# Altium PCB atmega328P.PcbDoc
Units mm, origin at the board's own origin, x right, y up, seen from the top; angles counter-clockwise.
Board outline 71.5 x 56.39 mm, 2 copper layers (Top Layer, Bottom Layer); 14 components, 27 nets, 83 pads, 0 vias.
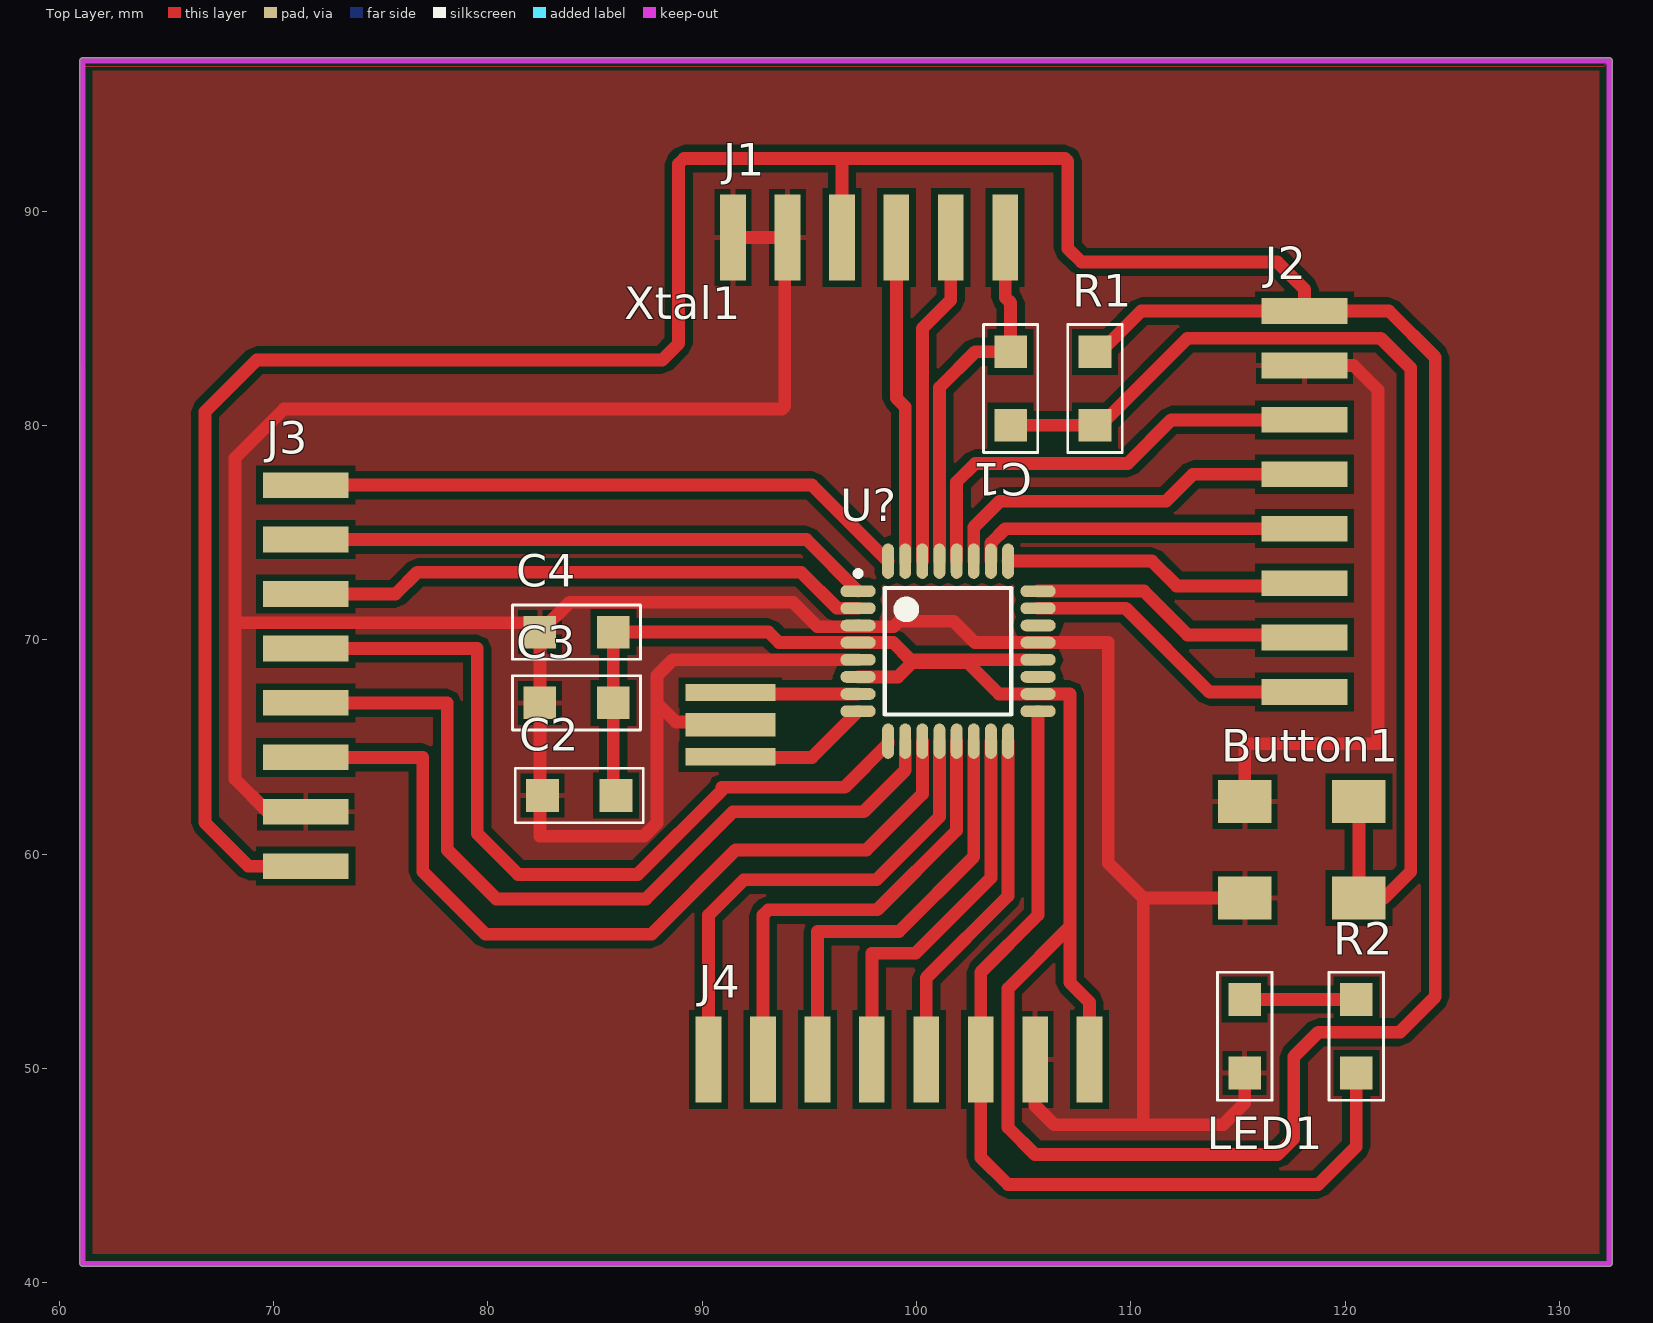
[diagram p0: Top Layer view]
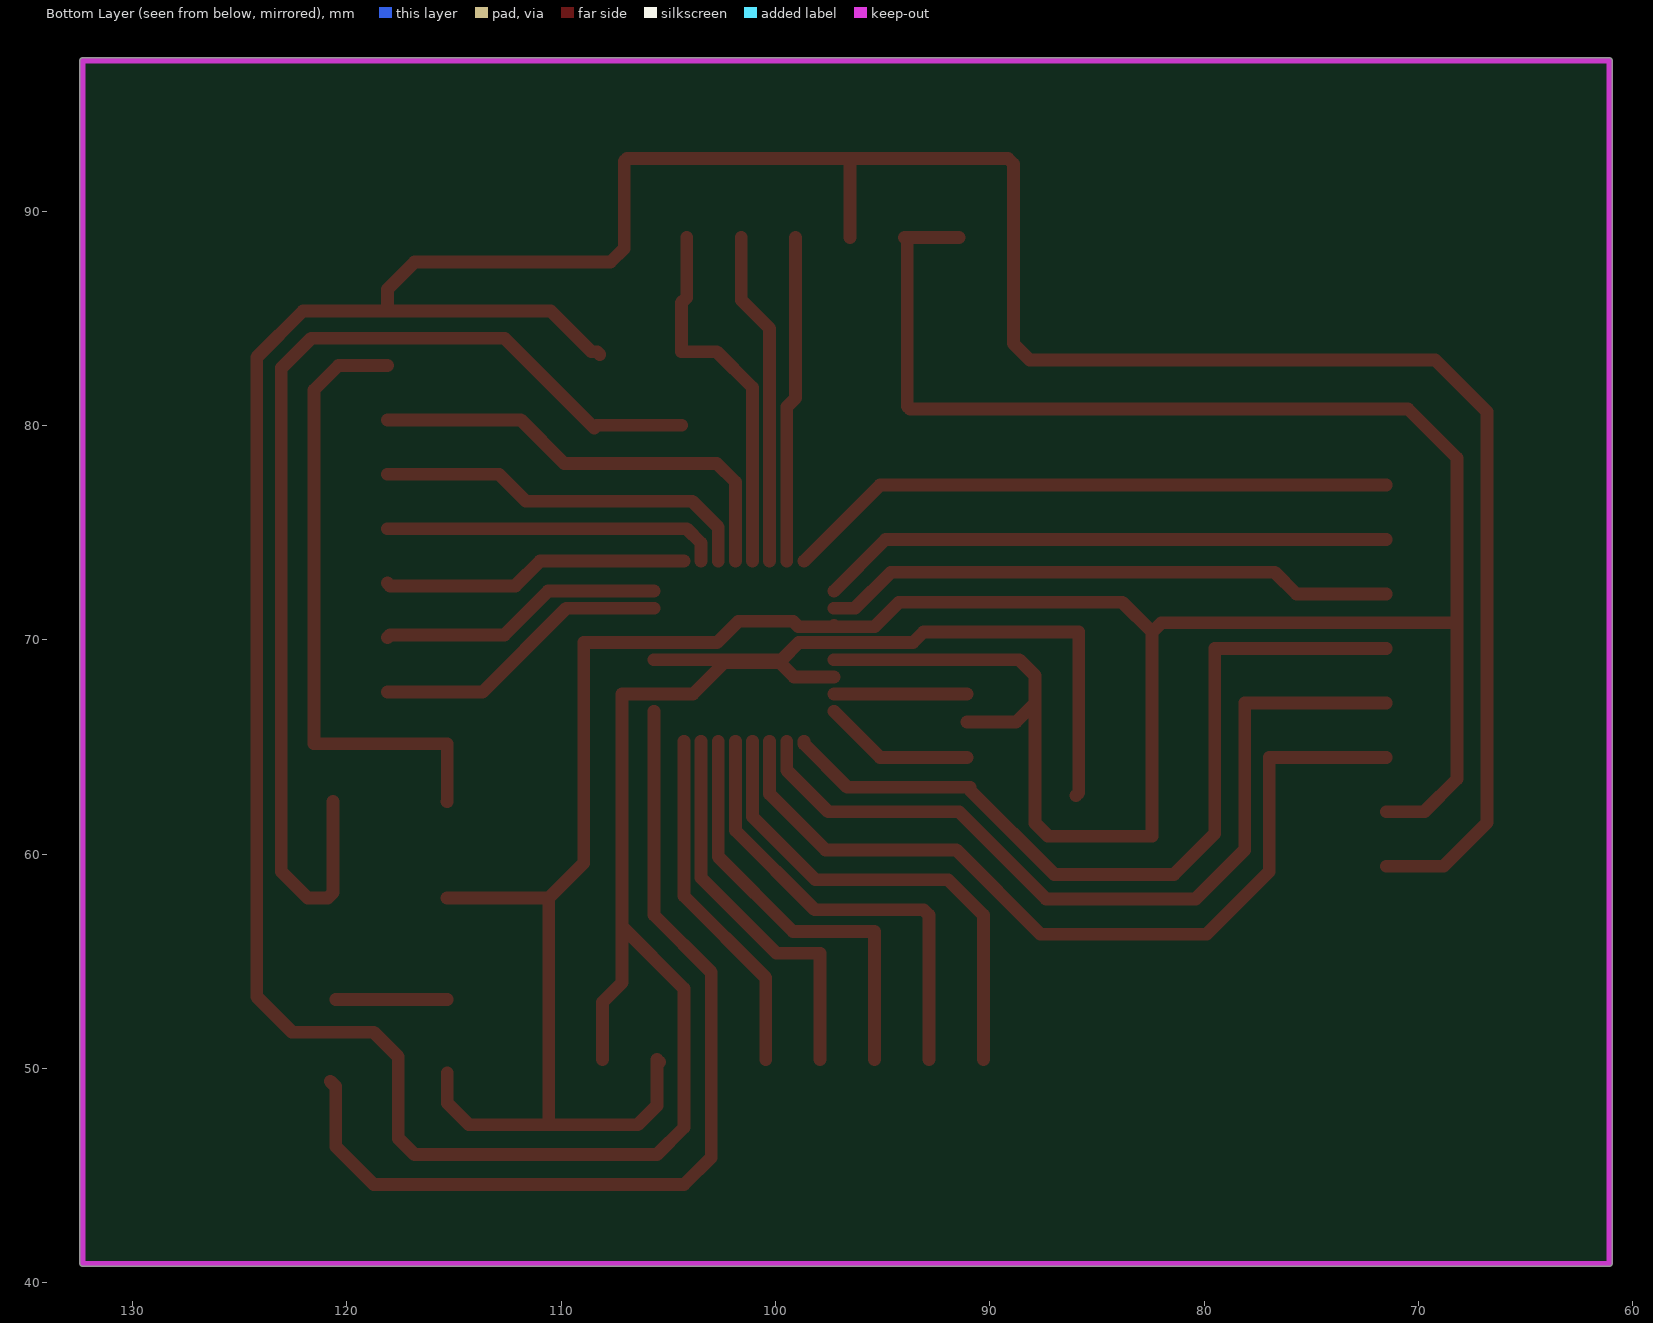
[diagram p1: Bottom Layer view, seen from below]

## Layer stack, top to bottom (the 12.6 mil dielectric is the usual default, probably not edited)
Top Solder: solder mask 0.0102, Solder Resist, Dk 3.5
Top Layer: signal copper 0.0356
Dielectric 1: dielectric 0.32, FR-4, Dk 4.8
Bottom Layer: signal copper 0.0356
Bottom Solder: solder mask 0.0102, Solder Resist, Dk 3.5

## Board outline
60.96,40.894 ccw(c61.087,40.894) 61.087,40.767 132.334,40.767 ccw(c132.334,40.894) 132.461,40.894 132.461,97.028 ccw(c132.334,97.028) 132.334,97.155 61.087,97.155 ccw(c61.087,97.028) 60.96,97.028

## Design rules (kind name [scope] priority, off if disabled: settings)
Clearance [All] p1: gap=0.3
PolygonConnect [All] p1: connectstyle=Relief reliefconductorwidth=0.254 reliefentries=4 polygonreliefangle="90 Angle" airgapwidth=0.254
RoutingLayers [All] p1: top layer_v5=TRUE bottom layer_v5=FALSE
RoutingVias [All] p1: holewidth=0.711 width=1.27 viastyle="Through Hole" minholewidth=0.711 minwidth=1.27 maxholewidth=0.711 maxwidth=1.27
SolderMaskExpansion [All] p1: expansion=0.102
Width [All] p1: maxlimit=0.6 minlimit=0.4 preferedwidth=0.6
29 further rules are at their usual default settings.

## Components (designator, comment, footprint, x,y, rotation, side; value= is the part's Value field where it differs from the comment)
Button1 "Button" smdbutton 117.983,60.198 r0 top
C1 "1UF" 1206C-GENERIC 104.394,83.439 r270 top
C2 "10UF" 1206C-GENERIC 85.979,62.738 r180 top
C3 "1UF" 1206C-GENERIC 85.852,67.056 r180 top
C4 ".1UF" 1206C-GENERIC 85.852,70.358 r180 top
J1 "J" "ftdiJumper 1x6" 96.52,88.773 r90 top
J2 "jumper1x8" jumper1x8 118.11,85.344 r0 top
J3 "jumper1x8" jumper1x8 71.501,59.436 r180 top
J4 "jumper1x8" jumper1x8 108.077,50.419 r270 top
LED1 "" 1206C-GENERIC 115.316,53.213 r270 top
R1 "10K" 1206C-GENERIC 108.331,83.439 r270 top
R2 "499" 1206C-GENERIC 120.523,49.784 r90 top
U? "ATmega328P-AU" 32A_N 101.473,69.469 r0 top
Xtal1 "Xtal" smdXtalEcs-cr2-b 91.313,66.04 r90 top

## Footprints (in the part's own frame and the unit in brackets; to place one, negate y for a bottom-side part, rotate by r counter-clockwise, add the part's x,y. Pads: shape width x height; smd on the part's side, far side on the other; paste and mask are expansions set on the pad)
32A_N [mm] "Thin QFP, 32-Leads, Body 7x7mm, Pitch 0.8mm, IPC Medium Density"
  oval 1.65x0.55 smd: 1(-4.2,2.8) 2(-4.2,2) 3(-4.2,1.2) 4(-4.2,0.4) 5(-4.2,-0.4) 6(-4.2,-1.2) 7(-4.2,-2) 8(-4.2,-2.8) 17(4.2,-2.8) 18(4.2,-2) 19(4.2,-1.2) 20(4.2,-0.4) 21(4.2,0.4) 22(4.2,1.2) 23(4.2,2) 24(4.2,2.8)
  oval 0.55x1.65 smd: 9(-2.8,-4.2) 10(-2,-4.2) 11(-1.2,-4.2) 12(-0.4,-4.2) 13(0.4,-4.2) 14(1.2,-4.2) 15(2,-4.2) 16(2.8,-4.2) 25(2.8,4.2) 26(2,4.2) 27(1.2,4.2) 28(0.4,4.2) 29(-0.4,4.2) 30(-1.2,4.2) 31(-2,4.2) 32(-2.8,4.2)
  silkscreen extent -4.32,-2.95 2.95,3.75, body extent -3.5,-3.5 3.5,3.5, height 1.2
1206C-GENERIC [mil]
  rect 60x60 smd: 1(0,0) 2(135,0)
  silkscreen extent -50,-50 185,50, body extent -8,-29 147,29, height 46
"ftdiJumper 1x6" [mm]
  rect 4x1.2 smd: 0(0,5.08) 1(0,2.54) 2(0,0) 3(0,-2.54) 4(0,-5.08) 5(0,-7.62)
jumper1x8 [mm]
  rect 4x1.2 smd: 0(0,0) 1(0,-2.54) 2(0,-5.08) 3(0,-7.62) 4(0,-10.16) 5(0,-12.7) 6(0,-15.24) 7(0,-17.78)
smdbutton [mm]
  rect 2.5x2 smd: 0(-2.66,2.25) 1(-2.66,-2.25) 2(2.66,-2.25) 3(2.66,2.25)
smdXtalEcs-cr2-b [mm]
  rect 0.8x4.2 smd: 0(-1.5,0) 2(1.5,0)
  rect 1.1x4.2 smd: 1(0,0)

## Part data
Button1: library part smdbutton
C1 C2 C3 C4 LED1 R1 R2: library part 1206C-10U-35V-X7R, "GENERIC CAPACITOR NON POLARISED 1206"
J1: library part "ftdiJumper 1x6"
U?: "8-bit AVR Microcontroller, 32KB Flash, 1KB EEPROM, 2KB SRAM, 32-pin TQFP, Industrial Grade (-40°C to 85°C)"
Xtal1: library part smdXtalEcs-cr2-B

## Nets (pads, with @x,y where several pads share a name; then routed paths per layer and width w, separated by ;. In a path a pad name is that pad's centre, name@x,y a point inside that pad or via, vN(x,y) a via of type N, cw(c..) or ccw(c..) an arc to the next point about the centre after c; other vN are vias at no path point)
GND: Button1.0 Button1.1 C2.2 C3.2 C4.2 J1.0 J1.1 J2.1 J3.1 J4.1 LED1.2 U?.3 U?.5 U?.21 Xtal1.1 | length 205.5
  Top Layer w0.6: 68.199,70.796 81.985,70.796 C4.2 ; J3.1 69.723,61.976 68.199,63.5 68.199,78.486 70.485,80.772 93.726,80.772 93.853,80.899 93.853,88.646 J1.1 J1.0 ; Xtal1.1@91.059,66.167 88.773,66.167 87.884,67.056 ; U?.5 88.627,69.069 87.884,68.326 87.884,67.056 ; J4.1@105.417,50.299 J4.1 105.537,48.26 106.426,47.371 114.3,47.371 115.316,48.387 LED1.2 ; 110.581,47.407 110.581,57.948 ; Button1.1 110.581,57.948 ; Button1.0 115.316,62.455 115.316,65.151 121.539,65.151 121.539,81.661 120.396,82.804 J2.1 ; C4.2 83.82,71.755 94.234,71.755 95.377,70.612 97.216,70.612 U?.3 97.33,70.612 98.933,70.612 99.187,70.866 101.727,70.866 102.724,69.869 U?.21 108.947,69.869 108.947,59.582 110.581,57.948 ; C4.2 C3.2 82.423,60.833 87.276,60.833 87.884,61.441 87.884,67.056
NetButton1_2: Button1.2 Button1.3 C1.2 R1.2 | length 51.6
  Top Layer w0.6: C1.2 R1.2 ; R1.2@108.458,79.883 112.649,84.074 121.666,84.074 123.063,82.677 123.063,59.182 121.829,57.948 120.897,57.948 120.643,58.202 Button1.3
NetC1_1: C1.1 J1.5 U?.29 | length 17.6
  Top Layer w0.6: U?.29 101.073,81.769 102.743,83.439 C1.1 104.394,85.725 104.14,85.979 J1.5
NetJ1_3: J1.3 U?.31 | length 15.3
  Top Layer w0.6: J1.3 99.06,81.28 99.473,80.867 U?.31
NetJ1_4: J1.4 U?.30 | length 15.7
  Top Layer w0.6: U?.30 100.273,84.525 101.6,85.852 J1.4
NetJ2_2: J2.2 U?.28 | length 21.1
  Top Layer w0.6: U?.28 101.873,77.362 102.743,78.232 109.855,78.232 111.887,80.264 J2.2
NetJ2_3: J2.3 U?.27 | length 18
  Top Layer w0.6: U?.27 102.673,75.254 103.886,76.467 111.646,76.467 112.903,77.724 J2.3
NetJ2_4: J2.4 U?.26 | length 15.8
  Top Layer w0.6: U?.26 103.473,74.517 104.14,75.184 J2.4
NetJ2_5: J2.5 U?.25 | length 14.4
  Top Layer w0.6: U?.25 110.989,73.669 112.141,72.517 117.983,72.517 J2.5
NetJ2_6: J2.6 U?.24 | length 13.3
  Top Layer w0.6: U?.24 110.611,72.269 112.649,70.231 117.983,70.231 J2.6
NetJ2_7: J2.7 U?.23 | length 14.1
  Top Layer w0.6: U?.23 109.76,71.469 113.665,67.564 J2.7
NetJ3_2: J3.2 U?.11 | length 40.5
  Top Layer w0.6: J3.2 76.962,64.516 76.962,59.182 79.883,56.261 87.63,56.261 91.567,60.198 97.663,60.198 100.273,62.808 U?.11
NetJ3_3: J3.3 U?.10 | length 39.6
  Top Layer w0.6: J3.3 78.105,67.056 78.105,60.198 80.391,57.912 87.376,57.912 91.44,61.976 97.536,61.976 99.473,63.913 U?.10
NetJ3_4: J3.4 U?.9 | length 39.3
  Top Layer w0.6: J3.4 79.502,69.596 79.502,60.96 81.407,59.055 86.995,59.055 90.932,62.992 90.932,63.119 96.647,63.119 98.673,65.145 U?.9
NetJ3_5: J3.5 U?.2 | length 26.9
  Top Layer w0.6: J3.5 75.692,72.136 76.708,73.152 94.615,73.152 96.298,71.469 U?.2
NetJ3_6: J3.6 U?.1 | length 26.8
  Top Layer w0.6: J3.6 94.866,74.676 U?.1
NetJ3_7: J3.7 U?.32 | length 28.6
  Top Layer w0.6: J3.7 95.126,77.216 U?.32
NetJ4_2: J4.2 R2.1 U?.17 | length 43.9
  Top Layer w0.6: U?.17 105.673,57.159 102.997,54.483 J4.2 102.997,45.847 104.267,44.577 118.745,44.577 120.523,46.355 120.523,49.149 R2.1@120.777,49.403
NetJ4_3: J4.3 U?.16 | length 16.4
  Top Layer w0.6: J4.3 100.457,54.229 104.273,58.045 U?.16
NetJ4_4: J4.4 U?.15 | length 18.3
  Top Layer w0.6: J4.4 97.917,55.372 99.949,55.372 103.473,58.896 U?.15
NetJ4_5: J4.5 U?.14 | length 20.1
  Top Layer w0.6: J4.5 95.377,56.388 99.187,56.388 102.673,59.874 U?.14
NetJ4_6: J4.6 U?.13 | length 21.6
  Top Layer w0.6: J4.6 92.837,57.15 93.091,57.404 98.171,57.404 101.873,61.106 U?.13
NetJ4_7: J4.7 U?.12 | length 22.9
  Top Layer w0.6: J4.7 90.297,57.15 91.948,58.801 98.133,58.801 101.073,61.741 U?.12
NetLED1_1: LED1.1 R2.2 | length 5.2
  Top Layer w0.6: LED1.1 R2.2
NetU?_7: U?.7 Xtal1.2 | length 6.2
  Top Layer w0.6: Xtal1.2@91.059,67.469 U?.7
NetU?_8: U?.8 Xtal1.0 | length 7.1
  Top Layer w0.6: Xtal1.0@91.059,64.516 95.12,64.516 U?.8
VCC: C2.1 C3.1 C4.1 J1.2 J2.0 J3.0 J4.0 R1.1 U?.4 U?.6 U?.18 U?.20 | length 235.6
  Top Layer w0.6: J3.0 68.834,59.436 66.802,61.468 66.802,80.645 69.215,83.058 88.138,83.058 88.9,83.82 88.9,92.202 89.154,92.456 96.52,92.456 ; C2.1 85.852,62.865 C3.1 C4.1 93.091,70.358 93.58,69.869 U?.4 98.914,69.869 99.714,69.069 U?.20 ; J1.2 96.52,92.456 ; U?.6 99.13,68.269 99.803,68.942 102.381,68.942 103.854,67.469 U?.18 107.156,67.469 107.156,56.61 ; J4.0 108.077,53.086 107.156,54.007 107.156,56.61 ; R1.1@108.204,83.312 R1.1 108.585,83.439 110.49,85.344 J2.0 ; 96.52,92.456 106.934,92.456 107.061,92.329 107.061,88.265 107.696,87.63 116.84,87.63 118.11,86.36 J2.0 ; 107.156,56.61 104.267,53.721 104.267,47.244 105.537,45.974 116.84,45.974 117.602,46.736 117.602,50.546 118.745,51.689 122.555,51.689 124.206,53.34 124.206,83.185 122.047,85.344 J2.0
pads on no net: U?.19 U?.22

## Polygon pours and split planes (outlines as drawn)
GND on Top Layer "NONET_L01_P-001" (solid, pour order 16): 61.087,97.028 132.334,97.028 132.334,40.894 61.087,40.894
GND on Top Layer "NONET_L01_P-001" (solid, shelved, pour order 14): 61.087,97.028 132.334,97.028 132.334,40.894 61.087,40.894
GND on Top Layer "NONET_L01_P-001" (solid, shelved, pour order 12): 61.087,97.028 132.334,97.028 132.334,40.894 61.087,40.894
GND on Top Layer "NONET_L01_P-001" (solid, shelved, pour order 10): 61.087,96.774 132.08,96.774 132.334,97.028 132.334,40.894 61.214,40.894 60.96,41.148

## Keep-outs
Keep-Out Layer:
  lines w0.254: 61.087,40.894 61.087,97.028 132.334,97.028 132.334,40.894 61.087,40.894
